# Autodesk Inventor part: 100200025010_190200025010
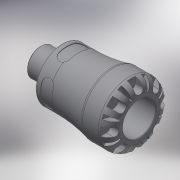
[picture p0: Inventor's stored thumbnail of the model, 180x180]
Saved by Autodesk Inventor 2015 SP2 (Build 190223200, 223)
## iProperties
Created: 2016-12
Part Number: 100200025010_190200025010
Material: Generic
Description: PLASSON MALE ADAPTOR 25X1" SERIES 1
Document SubType Name: Modeling
Designer: KIM
Mass: 447.839 g
Surface Area: 722.341 cm^2
Volume: 447.839 cm^3
Density: 1 g/cm^3
Appearance: Default
Author: KIM
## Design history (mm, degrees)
derived "1002.ipt"
feature "Solid1::1002.ipt"
tag "TaggingFeature1"
body "Solid1"
other parameters: "d0" = 78, "d1" = 20.16, "d2" = 25, "d3" = 31.25, "d4" = 47, "d6" = 48, "d8" = 39.95, "d13" = 6.3, "d14" = 6.3, "d15" = 0, "d17" = 360 deg, "d19" = 8 deg, "d20" = 0.5, "d21" = 0.5, "d22" = 8 deg, "d24" = 0, "d26" = 360 deg, "d32" = 0.925, "d33" = 4.7, "d34" = 33.249, "d35" = 2.08333, "d38" = 19, "d39" = 0.99747, "d42" = 8.75, "d43" = 5.75, "d45" = 12.348, "d46" = 0, "d59" = 360 deg, "d61" = 7.4375, "d62" = 0.5, "d64" = 0, "d65" = 0.47, "d_" = 25, "E_" = 47, "H_" = 78, "l_" = 48, "R_" = 33.249, "l_2" = 19, "d9" = 7.875, "d11" = 47, "d12" = 31.25
